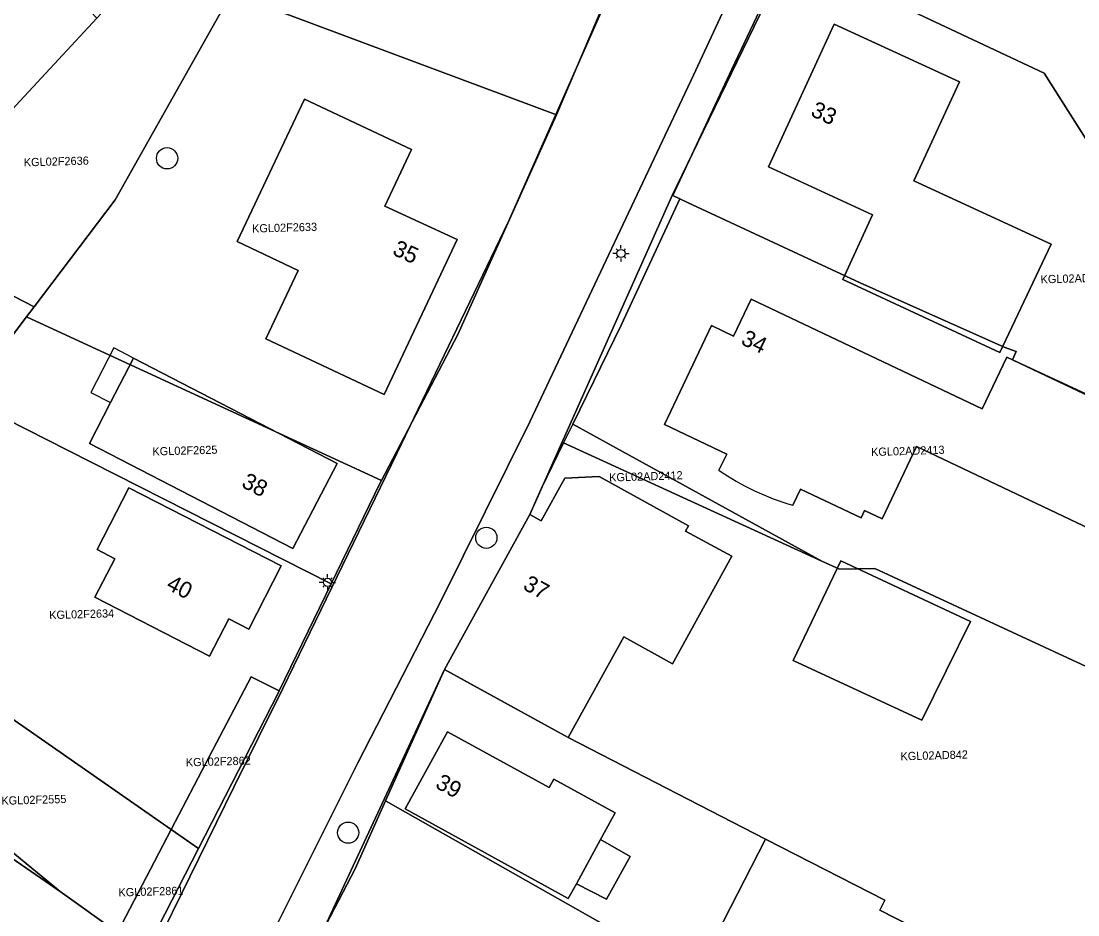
# Model space of a CAD drawing. Extents: x 124901 to 125496, y 515369 to 515789.
# Drawn here: x 125106.1 to 125170.8, y 515689 to 515743.7 of the extents above; entities that cross this region are included whole.
import ezdxf

# ---------------------------------------------------------------- set-up
doc = ezdxf.new("R2010")
doc.units = 0
for name, color, linetype in [('Gebouw', 7, 'Continuous'), ('Lichtmast', 7, 'Continuous'), ('Luifel', 7, 'Continuous'), ('Onbegroeid terrein', 7, 'Continuous'), ('Perceelnummers', 7, 'Continuous'), ('Perceelsgrenzen', 7, 'Continuous'), ('Putten', 7, 'Continuous'), ('Teksten', 7, 'Continuous'), ('Voetpad', 7, 'Continuous'), ('Wegen lokale weg', 7, 'Continuous')]:
    doc.layers.add(name, color=color, linetype=linetype)

msp = doc.modelspace()

# ---------------------------------------------------------------- linework, layer by layer
at = {"layer": 'Gebouw'}
for points in [[(125158.25, 515731.801), (125156.429, 515727.846), (125166.041, 515723.369), (125169.179, 515730.011), (125160.787, 515733.881), (125163.58, 515739.938), (125155.916, 515743.473), (125151.89, 515734.729)], [(125119.367, 515730.16), (125123.101, 515728.395), (125121.126, 515724.218), (125128.359, 515720.799), (125132.833, 515730.287), (125128.404, 515732.336), (125130.036, 515735.79), (125123.491, 515738.884)], [(125122.779, 515711.366), (125125.478, 515716.584), (125113.025, 515723.026), (125111.617, 515720.302), (125110.326, 515717.807)], [(125146.811, 515712.442), (125146.987, 515712.762), (125141.521, 515715.773), (125139.415, 515715.672), (125137.978, 515713.064), (125137.276, 515713.452), (125132.057, 515703.978), (125133.209, 515703.343), (125139.631, 515699.806), (125143.023, 515705.964), (125146.004, 515704.321), (125149.634, 515710.909)], [(125122.06, 515710.305), (125112.743, 515715.097), (125110.792, 515711.304), (125111.87, 515710.75), (125110.658, 515708.394), (125117.684, 515704.781), (125118.862, 515707.071), (125120.076, 515706.447)], [(125156.317, 515710.625), (125153.393, 515704.511), (125161.278, 515700.861), (125164.256, 515706.904)], [(125138.748, 515697.265), (125138.463, 515696.747), (125132.248, 515700.16), (125129.653, 515695.435), (125139.633, 515689.955), (125140.129, 515690.858), (125141.613, 515693.56), (125142.512, 515695.198)], [(125143.43, 515692.518), (125141.613, 515693.56), (125140.129, 515690.858), (125141.975, 515689.906)], [(125151.696, 515693.579), (125147.852, 515686.046), (125154.955, 515682.421), (125155.273, 515683.044), (125162.521, 515679.346), (125165.732, 515685.639), (125158.693, 515689.231), (125159.008, 515689.848)]]:
    msp.add_lwpolyline(points, close=True, dxfattribs=at)
msp.add_lwpolyline([(125153.374, 515714.021), (125153.846, 515715.015), (125157.55, 515713.258), (125157.764, 515713.709), (125158.848, 515713.195), (125160.949, 515717.622), (125172.378, 515712.199), (125175.507, 515718.795), (125166.472, 515723.081), (125164.972, 515719.919), (125150.824, 515726.632), (125149.752, 515724.373), (125148.397, 515725.016), (125145.525, 515718.963), (125149.328, 515717.158), (125148.857, 515716.164)], dxfattribs=at)
msp.add_arc((125157.675, 515728.919), 15.507, 235.34193, 253.89595, dxfattribs=at)
at = {"layer": 'Lichtmast'}
for p, q in [((125142.643, 515729.645), (125142.573, 515729.716)), ((125142.855, 515729.733), (125142.855, 515729.933)), ((125143.067, 515729.645), (125143.138, 515729.717)), ((125142.555, 515729.434), (125142.355, 515729.433)), ((125142.643, 515729.221), (125142.571, 515729.15)), ((125142.855, 515729.133), (125142.855, 515728.933)), ((125143.067, 515729.221), (125143.137, 515729.15)), ((125143.155, 515729.433), (125143.355, 515729.433)), ((125124.68, 515709.512), (125124.61, 515709.583)), ((125124.892, 515709.6), (125124.892, 515709.8)), ((125125.104, 515709.512), (125125.175, 515709.584)), ((125124.592, 515709.301), (125124.392, 515709.3)), ((125124.68, 515709.088), (125124.608, 515709.017)), ((125124.892, 515709), (125124.892, 515708.8)), ((125125.104, 515709.088), (125125.174, 515709.017)), ((125125.192, 515709.3), (125125.392, 515709.3))]:
    msp.add_line(p, q, dxfattribs=at)
for centre in [(125142.855, 515729.433), (125124.892, 515709.3)]:
    msp.add_circle(centre, 0.25, dxfattribs=at)
at = {"layer": 'Luifel'}
msp.add_lwpolyline([(125111.814, 515723.652), (125110.406, 515720.929), (125111.617, 515720.302), (125113.025, 515723.026)], close=True, dxfattribs=at)
at = {"layer": 'Onbegroeid terrein'}
for points in [[(125172.005, 515767.951), (125164.373, 515771.625), (125164.103, 515771.101), (125162.164, 515767.334), (125161.657, 515767.511), (125154.38, 515752.131), (125155.101, 515751.776), (125153.09, 515747.63), (125147.541, 515736.188), (125145.997, 515732.977), (125137.276, 515713.452), (125137.978, 515713.064), (125139.415, 515715.672), (125141.521, 515715.773), (125146.987, 515712.762), (125146.811, 515712.442), (125149.634, 515710.909), (125146.004, 515704.321), (125143.023, 515705.964), (125139.631, 515699.806), (125133.209, 515703.343), (125132.057, 515703.978), (125122.249, 515682.88)], [(125114.857, 515687.989), (125119.179, 515696.811), (125122.168, 515702.811), (125129.13, 515717.194), (125135.973, 515731.393), (125144.609, 515750.907)], [(125148.857, 515716.164), (125149.328, 515717.158), (125145.525, 515718.963), (125148.397, 515725.016), (125149.752, 515724.373), (125150.824, 515726.632), (125164.972, 515719.919), (125166.472, 515723.081), (125175.507, 515718.795), (125177.695, 515717.757), (125174.566, 515711.161), (125172.378, 515712.199), (125160.949, 515717.622), (125158.848, 515713.195), (125157.764, 515713.709), (125157.55, 515713.258), (125153.846, 515715.015), (125153.374, 515714.021)]]:
    msp.add_lwpolyline(points, dxfattribs=at)
for points in [[(125156.429, 515727.846), (125158.25, 515731.801), (125151.89, 515734.729), (125155.916, 515743.473), (125163.58, 515739.938), (125160.787, 515733.881), (125169.179, 515730.011), (125166.041, 515723.369)], [(125119.367, 515730.16), (125123.491, 515738.884), (125130.036, 515735.79), (125128.404, 515732.336), (125132.833, 515730.287), (125128.359, 515720.799), (125121.126, 515724.218), (125123.101, 515728.395)], [(125125.478, 515716.584), (125122.779, 515711.366), (125110.326, 515717.807), (125111.617, 515720.302), (125113.025, 515723.026)], [(125112.743, 515715.097), (125122.06, 515710.305), (125120.076, 515706.447), (125118.862, 515707.071), (125117.684, 515704.781), (125110.658, 515708.394), (125111.87, 515710.75), (125110.792, 515711.304)], [(125153.393, 515704.511), (125156.317, 515710.625), (125164.256, 515706.904), (125161.278, 515700.861)], [(125141.613, 515693.56), (125143.43, 515692.518), (125141.975, 515689.906), (125140.129, 515690.858), (125139.633, 515689.955), (125129.653, 515695.435), (125132.248, 515700.16), (125138.463, 515696.747), (125138.748, 515697.265), (125142.512, 515695.198)], [(125147.852, 515686.046), (125151.696, 515693.579), (125159.008, 515689.848), (125158.693, 515689.231), (125165.732, 515685.639), (125162.521, 515679.346), (125155.273, 515683.044), (125154.955, 515682.421)]]:
    msp.add_lwpolyline(points, close=True, dxfattribs=at)
msp.add_arc((125157.675, 515728.919), 15.507, 235.34193, 253.89595, dxfattribs=at)
at = {"layer": 'Perceelsgrenzen'}
for points in [[(125113.735, 515686.647), (125116.999, 515693.015), (125121.887, 515702.551), (125121.945, 515702.67), (125125.12, 515709.211), (125128.118, 515715.387), (125128.201, 515715.545), (125132.871, 515724.472), (125138.922, 515737.912), (125144.277, 515750.555), (125144.365, 515750.763), (125151.468, 515765.749), (125152.949, 515768.875), (125156.203, 515775.74), (125160.138, 515784.043)], [(125170.723, 515784.043), (125164.824, 515772.601), (125164.351, 515771.635), (125162.165, 515767.173), (125161.532, 515767.441), (125158.19, 515760.294), (125154.24, 515751.848), (125154.775, 515751.601), (125153.027, 515747.884), (125149.651, 515740.707), (125146.026, 515732.974), (125146.469, 515732.779), (125142.898, 515725.078), (125139.906, 515718.982), (125139.344, 515717.837), (125137.985, 515715.068), (125137.276, 515713.452), (125132.057, 515703.978), (125128.453, 515695.933), (125126.585, 515691.761), (125122.019, 515683)]]:
    msp.add_lwpolyline(points, dxfattribs=at)
for points in [[(125136.543, 515780.704), (125138.051, 515779.195), (125143.26, 515773.975), (125134.042, 515762.66), (125131.481, 515758.153), (125144.277, 515750.555), (125138.922, 515737.912), (125122.736, 515743.957), (125119.004, 515745.351), (125113.933, 515747.245), (125116.749, 515750.212), (125122.675, 515756.453), (125122.736, 515756.517), (125125.941, 515762.146), (125136.52, 515780.727)], [(125085.247, 515757.153), (125092.048, 515763.617), (125110.771, 515743.837), (125106.082, 515738.783), (125104.427, 515737.002)], [(125187.033, 515726.823), (125181.47, 515729.84), (125172.61, 515734.4), (125168.766, 515740.47), (125153.027, 515747.884), (125154.775, 515751.601), (125154.24, 515751.848), (125158.19, 515760.294), (125170.403, 515754.476), (125170.532, 515754.746), (125174.81, 515752.708), (125199.189, 515741.106), (125212.2, 515730.749), (125211.845, 515730.131), (125205.167, 515720.086), (125203.792, 515717.823)], [(125187.033, 515726.823), (125185.954, 515718.332), (125186.437, 515715.305), (125188.155, 515716.36), (125195.464, 515711.337), (125201.139, 515713.453), (125198.52, 515709.14), (125197.874, 515707.953), (125184.068, 515714.928), (125166.821, 515722.932), (125167.043, 515723.435), (125166.317, 515723.701), (125157.502, 515727.638), (125146.929, 515732.544), (125146.469, 515732.779), (125146.026, 515732.974), (125149.651, 515740.707), (125153.027, 515747.884), (125168.766, 515740.47), (125172.61, 515734.4), (125181.47, 515729.84)], [(125110.771, 515743.837), (125113.933, 515747.245), (125119.004, 515745.351), (125111.899, 515732.726), (125106.94, 515726.176), (125098.443, 515730.562), (125104.427, 515737.002), (125106.082, 515738.783)], [(125106.94, 515726.176), (125111.899, 515732.726), (125119.004, 515745.351), (125122.736, 515743.957), (125138.922, 515737.912), (125132.871, 515724.472), (125128.201, 515715.545), (125111.556, 515723.213), (125106.471, 515725.556)], [(125142.898, 515725.078), (125146.469, 515732.779), (125146.929, 515732.544), (125157.502, 515727.638), (125166.317, 515723.701), (125167.043, 515723.435), (125166.821, 515722.932), (125184.068, 515714.928), (125183.065, 515712.767), (125181.45, 515713.516), (125176.083, 515701.951), (125158.392, 515710.161), (125156.223, 515710.107), (125155.15, 515710.599), (125139.906, 515718.982)], [(125093.396, 515725.168), (125098.062, 515730.155), (125098.443, 515730.562), (125106.94, 515726.176), (125106.471, 515725.556), (125102.697, 515720.569), (125097.626, 515723.056), (125094.872, 515724.431)], [(125102.697, 515720.569), (125106.471, 515725.556), (125111.556, 515723.213), (125128.201, 515715.545), (125128.118, 515715.387), (125125.12, 515709.211), (125108.98, 515717.386)], [(125096.765, 515712.732), (125102.697, 515720.569), (125108.98, 515717.386), (125125.12, 515709.211), (125121.945, 515702.67), (125120.226, 515703.521), (125117.682, 515698.656), (125115.337, 515694.17), (125100.976, 515704.144), (125097.423, 515706.611), (125093.954, 515709.02)], [(125139.906, 515718.982), (125155.15, 515710.599), (125139.344, 515717.837)], [(125137.276, 515713.452), (125137.985, 515715.068), (125139.344, 515717.837), (125155.15, 515710.599), (125156.223, 515710.107), (125158.392, 515710.161), (125176.083, 515701.951), (125186.062, 515697.321), (125178.006, 515680.755), (125177.522, 515679.612), (125176.942, 515679.918), (125158.693, 515689.231), (125159.008, 515689.848), (125151.696, 515693.579), (125139.631, 515699.806), (125132.057, 515703.978)], [(125086.431, 515705.598), (125091.672, 515707.334), (125093.097, 515708.081), (125093.551, 515708.487), (125093.954, 515709.02), (125097.423, 515706.611), (125100.976, 515704.144), (125100.225, 515703.457), (125098.704, 515699.274), (125103.66, 515694.375), (125108.544, 515690.373)], [(125081.473, 515685.414), (125074.421, 515689.851), (125062.069, 515697.48), (125063.132, 515697.834), (125063.426, 515697.932), (125086.431, 515705.598), (125108.544, 515690.373), (125112.041, 515687.866), (125113.735, 515686.647), (125112.864, 515684.95), (125105.41, 515670.408), (125105.386, 515670.369)], [(125112.041, 515687.866), (125108.544, 515690.373), (125103.66, 515694.375), (125098.704, 515699.274), (125100.225, 515703.457), (125100.976, 515704.144), (125115.337, 515694.17)], [(125174.097, 515673.025), (125147.554, 515685.104), (125128.453, 515695.933), (125132.057, 515703.978), (125139.631, 515699.806), (125151.696, 515693.579), (125159.008, 515689.848), (125158.693, 515689.231), (125176.942, 515679.918), (125177.522, 515679.612), (125177.203, 515678.859)], [(125116.999, 515693.015), (125115.337, 515694.17), (125117.682, 515698.656), (125120.226, 515703.521), (125121.945, 515702.67), (125121.887, 515702.551)], [(125166.926, 515659.032), (125140.083, 515670.591), (125140.316, 515671.134), (125132.566, 515674.471), (125120.79, 515679.928), (125122.019, 515683), (125126.585, 515691.761), (125128.453, 515695.933), (125147.554, 515685.104), (125174.097, 515673.025), (125174.35, 515672.91), (125167.115, 515658.839)], [(125112.041, 515687.866), (125115.337, 515694.17), (125116.999, 515693.015), (125113.735, 515686.647)]]:
    msp.add_lwpolyline(points, close=True, dxfattribs=at)
at = {"layer": 'Putten'}
for centre in [(125115.08, 515735.26), (125134.62, 515712.03), (125126.16, 515693.98)]:
    msp.add_circle(centre, 0.65, dxfattribs=at)
at = {"layer": 'Voetpad'}
for points in [[(125168.476, 515784.043), (125158.271, 515763.978), (125147.289, 515740.344), (125137.289, 515719.132), (125131.829, 515708.15), (125126.75, 515698.247), (125121.195, 515687.161)], [(125122.249, 515682.88), (125132.057, 515703.978), (125137.276, 515713.452), (125145.997, 515732.977), (125147.541, 515736.188), (125153.09, 515747.63), (125155.101, 515751.776), (125154.38, 515752.131), (125161.657, 515767.511), (125162.164, 515767.334), (125164.103, 515771.101), (125164.373, 515771.625), (125165.906, 515774.602), (125166.739, 515776.22), (125168.314, 515779.28), (125170.766, 515784.043)]]:
    msp.add_lwpolyline(points, dxfattribs=at)
at = {"layer": 'Wegen lokale weg'}
msp.add_lwpolyline([(125152.686, 515766.719), (125152.224, 515766.949), (125146.998, 515755.898), (125145.256, 515752.258), (125144.609, 515750.907), (125135.973, 515731.393), (125129.13, 515717.194), (125122.168, 515702.811), (125119.179, 515696.811), (125114.857, 515687.989), (125110.211, 515678.634), (125109.5, 515677.38), (125114.841, 515674.77), (125114.87, 515674.83), (125121.195, 515687.161), (125126.75, 515698.247), (125131.829, 515708.15), (125137.289, 515719.132), (125147.289, 515740.344), (125158.271, 515763.978), (125168.476, 515784.043)], dxfattribs=at)

# ---------------------------------------------------------------- texts
at = {"layer": 'Perceelnummers'}
for s, rotation, p in [('KGL02F2636', 1.6311, (125106.315, 515734.762)), ('KGL02F2633', 1.63127, (125120.288, 515730.708)), ('KGL02AD980', 1.63183, (125168.547, 515727.6)), ('KGL02F2625', 1.6312, (125114.189, 515717.065)), ('KGL02AD2413', 1.8299, (125158.174, 515717.03)), ('KGL02AD2412', 1.82971, (125142.143, 515715.471)), ('KGL02F2634', 1.63112, (125107.87, 515707.051)), ('KGL02F2862', 1.63122, (125116.232, 515698.035)), ('KGL02AD842', 1.63173, (125159.973, 515698.406)), ('KGL02F2555', 1.63109, (125104.944, 515695.686)), ('KGL02F2861', 1.63117, (125112.111, 515690.074))]:
    msp.add_text(s, height=0.5, rotation=rotation, dxfattribs=at).set_placement(p)
at = {"layer": 'Teksten'}
for s, rotation, p in [('33', 335.3, (125154.408, 515737.884)), ('35', 335.2, (125128.813, 515729.392)), ('34', 334.6, (125150.139, 515723.906)), ('38', 332.6, (125119.571, 515715.175)), ('40', 332.8, (125114.966, 515708.921)), ('37', 331.2, (125136.795, 515708.92)), ('39', 331.2, (125131.436, 515696.765))]:
    msp.add_text(s, height=1, rotation=rotation, dxfattribs=at).set_placement(p)

doc.saveas('drawing.dxf')
